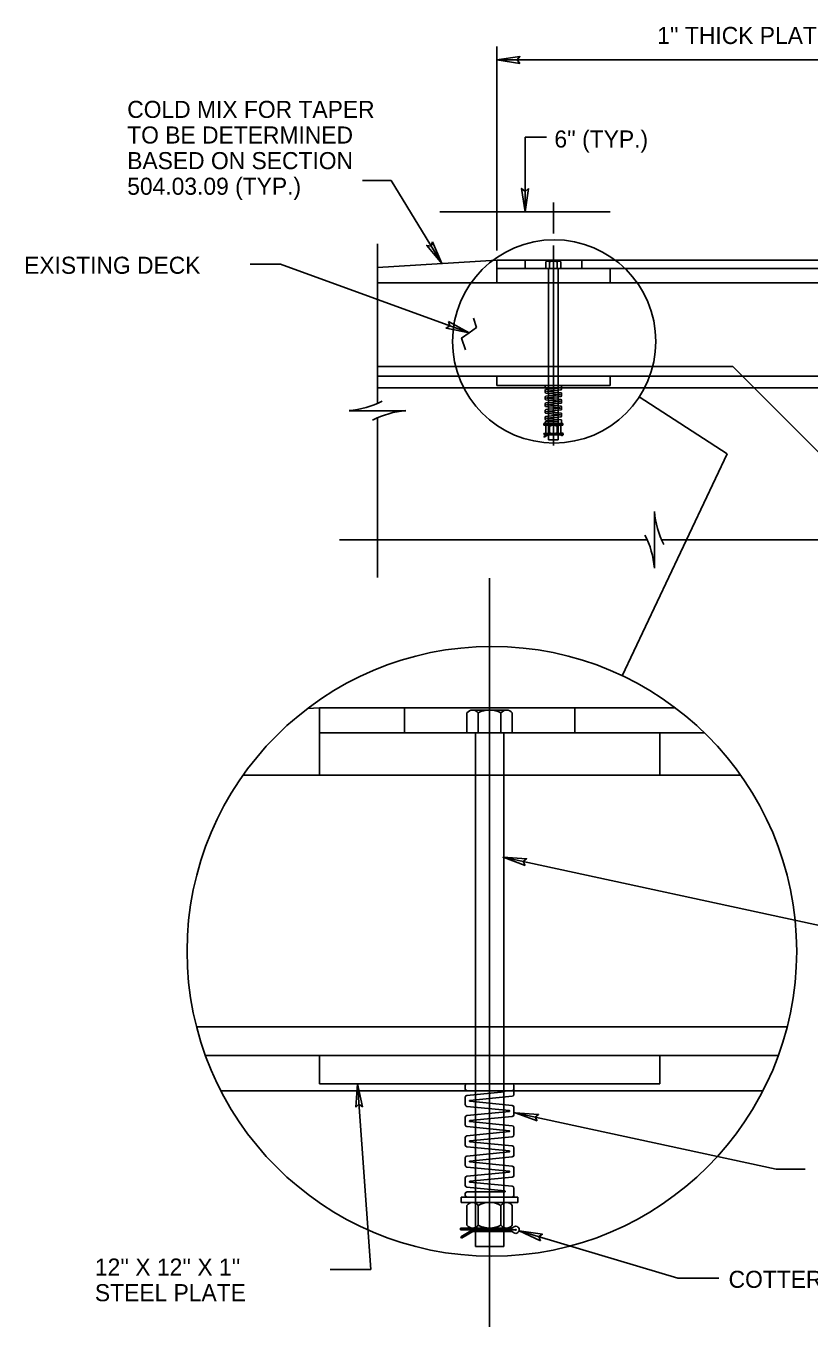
# Model space of a CAD drawing. Extents: x 12.49 to 19.62, y 5.98 to 15.32.
# Drawn here: x 12.777 to 15.532, y 10.469 to 15.04 of the extents above; entities that cross this region are included whole.
import ezdxf

# ---------------------------------------------------------------- set-up
doc = ezdxf.new("R2010")
doc.units = 0
for name, color, linetype in [('2', 7, 'Continuous'), ('Default', 7, 'Continuous'), ('DETL-DIMS', 7, 'Continuous'), ('DETL-NOTE', 7, 'Continuous'), ('V7_LEVEL_1', 7, 'Continuous')]:
    doc.layers.add(name, color=color, linetype=linetype)

msp = doc.modelspace()

# ---------------------------------------------------------------- linework, layer by layer
at = {"layer": '2'}
for p, q in [((14.232, 14.3875), (14.4313, 14.3875)), ((14.4313, 14.3875), (14.6305, 14.3875)), ((14.6305, 14.3875), (14.8298, 14.3875)), ((14.4313, 14.217), (14.0119, 14.192)), ((13.8084, 12.6445), (13.766, 12.6419))]:
    msp.add_line(p, q, dxfattribs=at)
for points in [[(13.9602, 14.4968), (14.0602, 14.4968), (14.2383, 14.2055)], [(13.5648, 14.2035), (13.6719, 14.2035), (14.3344, 13.9623)]]:
    msp.add_lwpolyline(points, dxfattribs=at)
at = {"layer": 'Default'}
for p, q in [((14.4313, 14.9686), (14.4313, 14.2511)), ((14.4313, 14.9207), (17.6199, 14.9207)), ((14.6305, 14.3117), (14.6305, 14.4197)), ((14.0119, 14.2752), (14.0119, 13.714)), ((14.6305, 13.5669), (14.6305, 14.2687)), ((14.4313, 14.217), (17.6199, 14.217)), ((14.4313, 14.1381), (14.4313, 14.217)), ((14.5309, 14.188), (14.5309, 14.217)), ((14.7302, 14.188), (14.7302, 14.217)), ((14.4313, 14.188), (14.8298, 14.188)), ((14.604, 14.188), (14.604, 14.2112)), ((14.6106, 14.2145), (14.6173, 14.2145)), ((14.6139, 13.6037), (14.6139, 14.188)), ((14.6173, 14.2145), (14.6438, 14.2145)), ((14.6173, 14.188), (14.6173, 14.2112)), ((14.6438, 14.2145), (14.6505, 14.2145)), ((14.6438, 14.188), (14.6438, 14.2112)), ((14.6471, 13.6037), (14.6471, 14.188)), ((14.6571, 14.188), (14.6571, 14.2112)), ((14.8298, 14.1381), (14.8298, 14.188)), ((14.8298, 14.188), (17.2213, 14.188)), ((14.0119, 14.1381), (14.4313, 14.1381)), ((14.4313, 14.1381), (17.6199, 14.1381)), ((14.0119, 13.8434), (15.2616, 13.8434)), ((14.0119, 13.8101), (14.4313, 13.8101)), ((14.4313, 13.7769), (14.4313, 13.8101)), ((14.4313, 13.8101), (14.8298, 13.8101)), ((14.8298, 13.7769), (14.8298, 13.8101)), ((14.8298, 13.8101), (15.9591, 13.8101)), ((15.5606, 13.5444), (15.2616, 13.8434)), ((14.0119, 13.7686), (15.9591, 13.7686)), ((14.4313, 13.7769), (14.8298, 13.7769)), ((14.6021, 13.7749), (14.6021, 13.7707)), ((14.6021, 13.7612), (14.6021, 13.7525)), ((14.6479, 13.7676), (14.604, 13.7633)), ((14.6571, 13.7622), (14.6074, 13.7574)), ((14.659, 13.7749), (14.659, 13.7643)), ((14.0285, 13.722), (14.0285, 13.722)), ((14.6021, 13.7375), (14.6021, 13.7288)), ((14.6021, 13.7139), (14.6021, 13.7051)), ((14.6537, 13.7455), (14.604, 13.7504)), ((14.6537, 13.7445), (14.604, 13.7396)), ((14.6537, 13.7218), (14.604, 13.7267)), ((14.6537, 13.7208), (14.604, 13.7159)), ((14.6571, 13.7514), (14.6074, 13.7563)), ((14.6571, 13.7386), (14.6074, 13.7337)), ((14.6571, 13.7278), (14.6074, 13.7326)), ((14.6571, 13.7149), (14.6074, 13.71)), ((14.659, 13.7494), (14.659, 13.7406)), ((14.659, 13.7257), (14.659, 13.717)), ((13.9123, 13.6887), (14.0119, 13.6887)), ((14.0119, 13.6887), (14.1116, 13.6887)), ((14.0119, 13.6887), (14.0119, 13.6887)), ((14.6021, 13.6902), (14.6021, 13.6814)), ((14.6021, 13.6665), (14.6021, 13.6578)), ((14.6537, 13.6982), (14.604, 13.703)), ((14.6537, 13.6971), (14.604, 13.6923)), ((14.6537, 13.6745), (14.604, 13.6794)), ((14.6537, 13.6735), (14.604, 13.6686)), ((14.6571, 13.7041), (14.6074, 13.709)), ((14.6571, 13.6912), (14.6074, 13.6863)), ((14.6571, 13.6804), (14.6074, 13.6853)), ((14.6571, 13.6675), (14.6074, 13.6627)), ((14.659, 13.702), (14.659, 13.6933)), ((14.659, 13.6783), (14.659, 13.6696)), ((13.9953, 13.6555), (13.9953, 13.6555)), ((14.0119, 13.6635), (14.0119, 13.1023)), ((14.5973, 13.6441), (14.6638, 13.6441)), ((14.5973, 13.6378), (14.5973, 13.6441)), ((14.5973, 13.6378), (14.6638, 13.6378)), ((14.6021, 13.6482), (14.6021, 13.6461)), ((14.6484, 13.6513), (14.604, 13.6557)), ((14.604, 13.6345), (14.604, 13.6113)), ((14.6042, 13.6503), (14.6484, 13.6503)), ((14.6571, 13.6567), (14.6074, 13.6616)), ((14.6173, 13.6345), (14.6173, 13.6113)), ((14.6438, 13.6345), (14.6438, 13.6113)), ((14.6571, 13.6345), (14.6571, 13.6113)), ((14.659, 13.6547), (14.659, 13.6461)), ((14.6638, 13.6378), (14.6638, 13.6441)), ((14.5965, 13.6079), (14.6565, 13.6079)), ((14.5965, 13.6058), (14.5965, 13.6079)), ((14.5965, 13.6058), (14.6606, 13.6058)), ((14.5967, 13.5978), (14.6104, 13.6058)), ((14.5967, 13.5978), (14.5978, 13.596)), ((14.5978, 13.596), (14.611, 13.6037)), ((14.6106, 13.6079), (14.6173, 13.6079)), ((14.611, 13.6037), (14.6565, 13.6037)), ((14.6139, 13.5861), (14.6139, 13.6037)), ((14.6139, 13.5861), (14.6471, 13.5861)), ((14.6173, 13.6079), (14.6438, 13.6079)), ((14.6438, 13.6079), (14.6505, 13.6079)), ((14.6471, 13.5861), (14.6471, 13.6037)), ((14.9855, 13.2352), (14.9855, 13.3348)), ((13.8791, 13.2352), (14.9603, 13.2352)), ((14.9523, 13.2518), (14.9523, 13.2518)), ((14.9855, 13.1356), (14.9855, 13.2352)), ((14.9855, 13.2352), (14.9855, 13.2352)), ((15.0108, 13.2352), (15.9591, 13.2352)), ((15.0187, 13.2186), (15.0187, 13.2186)), ((14.4063, 10.4694), (14.4063, 13.1007)), ((13.8084, 12.6445), (15.0594, 12.6445)), ((13.8084, 12.4078), (13.8084, 12.6445)), ((14.1074, 12.5573), (14.1074, 12.6445)), ((14.3266, 12.5573), (14.3266, 12.6268)), ((14.3466, 12.637), (14.3665, 12.637)), ((14.3665, 12.637), (14.4462, 12.637)), ((14.3665, 12.5573), (14.3665, 12.6268)), ((14.4462, 12.637), (14.4661, 12.637)), ((14.4462, 12.5573), (14.4462, 12.6268)), ((14.486, 12.5573), (14.486, 12.6268)), ((14.7053, 12.5573), (14.7053, 12.6445)), ((13.8084, 12.5573), (15.0042, 12.5573)), ((14.3565, 10.8046), (14.3565, 12.5573)), ((14.4561, 10.8046), (14.4561, 12.5573)), ((15.0042, 12.4078), (15.0042, 12.5573)), ((15.0042, 12.5573), (15.1611, 12.5573)), ((13.5398, 12.4078), (13.8084, 12.4078)), ((13.8084, 12.4078), (15.2889, 12.4078)), ((14.4538, 12.12), (15.7083, 11.8493)), ((13.3767, 11.5234), (15.452, 11.5234)), ((13.4074, 11.4238), (13.8084, 11.4238)), ((13.8084, 11.3242), (13.8084, 11.4238)), ((13.8084, 11.4238), (15.0042, 11.4238)), ((15.0042, 11.3242), (15.0042, 11.4238)), ((15.0042, 11.4238), (15.4213, 11.4238)), ((13.4618, 11.2992), (15.3669, 11.2992)), ((13.8084, 11.3242), (15.0042, 11.3242)), ((13.9889, 10.6709), (13.9419, 11.3242)), ((14.321, 11.3179), (14.321, 11.3055)), ((14.4583, 11.2961), (14.3266, 11.2832)), ((14.4917, 11.3179), (14.4917, 11.2863)), ((14.321, 11.277), (14.321, 11.2508)), ((14.4759, 11.2299), (14.3266, 11.2446)), ((14.486, 11.2801), (14.3368, 11.2654)), ((14.486, 11.2477), (14.3368, 11.2623)), ((14.321, 11.206), (14.321, 11.1797)), ((14.4759, 11.2268), (14.3266, 11.2122)), ((14.486, 11.2091), (14.3368, 11.1944)), ((14.4917, 11.2415), (14.4917, 11.2153)), ((14.4959, 11.2221), (15.4129, 11.0242)), ((14.4759, 11.1589), (14.3266, 11.1735)), ((14.4759, 11.1558), (14.3266, 11.1412)), ((14.486, 11.1767), (14.3368, 11.1913)), ((14.4917, 11.1705), (14.4917, 11.1442)), ((14.321, 11.135), (14.321, 11.1087)), ((14.486, 11.138), (14.3368, 11.1234)), ((14.486, 11.1056), (14.3368, 11.1203)), ((14.321, 11.0639), (14.321, 11.0377)), ((14.4759, 11.0879), (14.3266, 11.1025)), ((14.4759, 11.0848), (14.3266, 11.0701)), ((14.486, 11.067), (14.3368, 11.0524)), ((14.4917, 11.0994), (14.4917, 11.0732)), ((14.4759, 11.0168), (14.3266, 11.0315)), ((14.486, 11.0346), (14.3368, 11.0493)), ((14.4917, 11.0284), (14.4917, 11.0022)), ((15.4129, 11.0242), (15.5159, 11.0242)), ((14.321, 10.9929), (14.321, 10.9666)), ((14.4759, 11.0137), (14.3266, 10.9991)), ((14.486, 10.996), (14.3368, 10.9813)), ((14.486, 10.9636), (14.3368, 10.9782)), ((14.3067, 10.9256), (14.506, 10.9256)), ((14.3067, 10.9069), (14.3067, 10.9256)), ((14.321, 10.938), (14.321, 10.9318)), ((14.321, 10.938), (14.321, 10.9318)), ((14.46, 10.9474), (14.3266, 10.9604)), ((14.3272, 10.9443), (14.4598, 10.9443)), ((14.4917, 10.9574), (14.4917, 10.9318)), ((14.506, 10.9069), (14.506, 10.9256)), ((14.3067, 10.9069), (14.506, 10.9069)), ((14.3266, 10.8968), (14.3266, 10.8272)), ((14.3665, 10.8968), (14.3665, 10.8272)), ((14.4462, 10.8968), (14.4462, 10.8272)), ((14.486, 10.8968), (14.486, 10.8272)), ((14.3041, 10.8171), (14.4843, 10.8171)), ((14.3041, 10.8108), (14.3041, 10.8171)), ((14.3041, 10.8108), (14.4966, 10.8108)), ((14.3048, 10.7867), (14.346, 10.8108)), ((14.3048, 10.7867), (14.308, 10.7814)), ((14.308, 10.7814), (14.3477, 10.8046)), ((14.3466, 10.8171), (14.3665, 10.8171)), ((14.3477, 10.8046), (14.4843, 10.8046)), ((14.3565, 10.7517), (14.3565, 10.8046)), ((14.3665, 10.8171), (14.4462, 10.8171)), ((14.4462, 10.8171), (14.4661, 10.8171)), ((14.4561, 10.7517), (14.4561, 10.8046)), ((14.5101, 10.8072), (15.0677, 10.6411)), ((14.3565, 10.7517), (14.4561, 10.7517)), ((13.8466, 10.6709), (13.9889, 10.6709)), ((15.0677, 10.6411), (15.2117, 10.6411))]:
    msp.add_line(p, q, dxfattribs=at)
for centre, radius in [((14.6612, 13.6058), 0.000514), ((14.4982, 10.8108), 0.00154)]:
    msp.add_circle(centre, radius, dxfattribs=at)
for centre, radius, start, end in [((14.6106, 14.2063), 0.00822, 36.0721, 143.9279), ((14.6305, 14.1867), 0.0278, 61.4571, 118.5429), ((14.6505, 14.2063), 0.00822, 36.0721, 143.9279), ((14.6042, 13.7749), 0.00208, 90, 180), ((14.6042, 13.7707), 0.00208, 180, 270), ((14.6042, 13.7612), 0.00208, 95.6019, 180), ((14.6478, 13.7681), 0.000519, 275.6019, 90), ((14.6569, 13.7749), 0.00208, 0, 90), ((14.6569, 13.7707), 0.00208, 270, 0), ((14.6569, 13.7643), 0.00208, 275.6019, 0), ((13.8878, 13.9943), 0.3065, 274.5716, 297.3191), ((14.6042, 13.7525), 0.00208, 180, 264.3981), ((14.6042, 13.7375), 0.00208, 95.6019, 180), ((14.6042, 13.7288), 0.00208, 180, 264.3981), ((14.6042, 13.7139), 0.00208, 95.6019, 180), ((14.6074, 13.7568), 0.000519, 95.6019, 264.3982), ((14.6074, 13.7332), 0.000519, 95.6019, 264.3982), ((14.6537, 13.745), 0.000519, 275.6019, 84.3982), ((14.6537, 13.7213), 0.000519, 275.6019, 84.3982), ((14.6569, 13.7494), 0.00208, 360, 84.3981), ((14.6569, 13.7406), 0.00208, 275.6019, 0), ((14.6569, 13.7257), 0.00208, 360, 84.3981), ((14.6569, 13.717), 0.00208, 275.6019, 0), ((14.136, 13.3832), 0.3065, 94.5716, 117.3191), ((14.6042, 13.7051), 0.00208, 180, 264.3981), ((14.6042, 13.6902), 0.00208, 95.6019, 180), ((14.6042, 13.6814), 0.00208, 180, 264.3981), ((14.6042, 13.6665), 0.00208, 95.6019, 180), ((14.6074, 13.7095), 0.000519, 95.6019, 264.3982), ((14.6074, 13.6858), 0.000519, 95.6018, 264.3981), ((14.6537, 13.6976), 0.000519, 275.6019, 84.3982), ((14.6537, 13.674), 0.000519, 275.6019, 84.3982), ((14.6569, 13.702), 0.00208, 360, 84.3981), ((14.6569, 13.6933), 0.00208, 275.6018, 0), ((14.6569, 13.6783), 0.00208, 0, 84.3981), ((14.6569, 13.6696), 0.00208, 275.6019, 0), ((14.6042, 13.6578), 0.00208, 180, 264.3981), ((14.6042, 13.6482), 0.00208, 90, 180), ((14.6042, 13.6461), 0.00208, 180, 270), ((14.6106, 13.6296), 0.00822, 36.0721, 143.9279), ((14.6074, 13.6621), 0.000519, 95.6019, 264.3982), ((14.6305, 13.61), 0.0278, 61.4571, 118.5429), ((14.6505, 13.6296), 0.00822, 36.0721, 143.9279), ((14.6484, 13.6508), 0.000519, 270, 84.3981), ((14.6569, 13.6461), 0.00208, 270, 0), ((14.6569, 13.6547), 0.00208, 0, 84.3981), ((14.6106, 13.6161), 0.00822, 216.0721, 323.9279), ((14.6305, 13.6357), 0.0278, 241.4571, 298.5429), ((14.6505, 13.6161), 0.00822, 216.0721, 323.9279), ((14.6565, 13.61), 0.00208, 270, 318.007), ((14.6565, 13.6017), 0.00208, 41.6281, 90), ((14.6612, 13.6058), 0.00415, 221.6281, 138.007), ((15.2911, 13.3593), 0.3065, 184.5716, 207.3191), ((14.68, 13.1111), 0.3065, 4.5716, 27.3191), ((14.3466, 12.6123), 0.0246, 36.0721, 143.9279), ((14.4063, 12.5536), 0.0834, 61.4571, 118.5429), ((14.4661, 12.6123), 0.0246, 36.0721, 143.9279), ((14.3272, 11.3179), 0.00623, 90, 180), ((14.3272, 11.3055), 0.00623, 180, 270), ((14.4581, 11.2977), 0.00156, 275.6019, 90), ((14.4854, 11.3179), 0.00623, 0, 90), ((14.4854, 11.3055), 0.00623, 270, 0), ((14.3272, 11.277), 0.00623, 95.6019, 180), ((14.3272, 11.2508), 0.00623, 180, 264.3981), ((14.3369, 11.2639), 0.00156, 95.6019, 264.3982), ((14.4854, 11.2863), 0.00623, 275.6019, 0), ((14.4854, 11.2415), 0.00623, 360, 84.3981), ((14.3272, 11.206), 0.00623, 95.6019, 180), ((14.4757, 11.2284), 0.00156, 275.6019, 84.3982), ((14.4854, 11.2153), 0.00623, 275.6019, 0), ((14.3272, 11.1797), 0.00623, 180, 264.3981), ((14.3369, 11.1929), 0.00156, 95.6019, 264.3982), ((14.4757, 11.1573), 0.00156, 275.6019, 84.3982), ((14.4854, 11.1705), 0.00623, 360, 84.3981), ((14.3272, 11.135), 0.00623, 95.6019, 180), ((14.3272, 11.1087), 0.00623, 180, 264.3981), ((14.3369, 11.1218), 0.00156, 95.6019, 264.3982), ((14.4854, 11.1442), 0.00623, 275.6019, 0), ((14.3272, 11.0639), 0.00623, 95.6019, 180), ((14.4757, 11.0863), 0.00156, 275.6019, 84.3982), ((14.4854, 11.0994), 0.00623, 360, 84.3981), ((14.4854, 11.0732), 0.00623, 275.6018, 0), ((14.3272, 11.0377), 0.00623, 180, 264.3981), ((14.3369, 11.0508), 0.00156, 95.6018, 264.3981), ((14.4757, 11.0153), 0.00156, 275.6019, 84.3982), ((14.4854, 11.0284), 0.00623, 0, 84.3981), ((14.3272, 10.9929), 0.00623, 95.6019, 180), ((14.3369, 10.9798), 0.00156, 95.6019, 264.3982), ((14.4854, 11.0022), 0.00623, 275.6019, 0), ((14.3272, 10.9666), 0.00623, 180, 264.3981), ((14.3272, 10.938), 0.00623, 90, 180), ((14.3272, 10.9318), 0.00623, 180, 270), ((14.3272, 10.9318), 0.00623, 180, 270), ((14.4598, 10.9458), 0.00156, 270, 84.3981), ((14.4854, 10.9318), 0.00623, 270, 0), ((14.4854, 10.9318), 0.00623, 270, 0), ((14.4854, 10.9574), 0.00623, 0, 84.3981), ((14.3466, 10.8822), 0.0246, 36.0721, 143.9279), ((14.4063, 10.8235), 0.0834, 61.4571, 118.5429), ((14.4661, 10.8822), 0.0246, 36.0721, 143.9279), ((14.3466, 10.8417), 0.0246, 216.0721, 323.9279), ((14.4063, 10.9005), 0.0834, 241.4571, 298.5429), ((14.4661, 10.8417), 0.0246, 216.0721, 323.9279), ((14.4842, 10.7984), 0.00623, 41.6281, 90), ((14.4843, 10.8233), 0.00623, 270, 318.007), ((14.4982, 10.8108), 0.0125, 221.6281, 138.007)]:
    msp.add_arc(centre, radius, start, end, dxfattribs=at)
at = {"layer": 'DETL-DIMS'}
for p, q in [((14.5131, 14.9326), (14.4313, 14.9207)), ((14.5131, 14.9088), (14.4313, 14.9207)), ((14.5131, 14.9326), (14.503, 14.9207)), ((14.5131, 14.9088), (14.503, 14.9207)), ((14.519, 14.4693), (14.5309, 14.3875)), ((14.519, 14.4693), (14.5309, 14.4592)), ((14.5428, 14.4693), (14.5309, 14.3875)), ((14.5428, 14.4693), (14.5309, 14.4592)), ((14.1855, 14.2691), (14.2383, 14.2055)), ((14.1855, 14.2691), (14.2009, 14.2667)), ((14.2058, 14.2815), (14.2009, 14.2667)), ((14.2058, 14.2815), (14.2383, 14.2055)), ((14.2534, 13.9791), (14.267, 13.9868)), ((14.2616, 14.0014), (14.3344, 13.9623)), ((14.2616, 14.0014), (14.267, 13.9868)), ((14.2534, 13.9791), (14.3344, 13.9623)), ((14.5363, 12.1144), (14.4538, 12.12)), ((14.5313, 12.0911), (14.4538, 12.12)), ((14.5363, 12.1144), (14.5239, 12.1049)), ((14.5313, 12.0911), (14.5239, 12.1049)), ((13.9359, 11.2417), (13.9419, 11.3242)), ((13.9596, 11.2434), (13.9419, 11.3242)), ((13.9359, 11.2417), (13.947, 11.2526)), ((13.9596, 11.2434), (13.947, 11.2526)), ((14.5784, 11.2164), (14.4959, 11.2221)), ((14.5734, 11.1932), (14.4959, 11.2221)), ((14.5784, 11.2164), (14.566, 11.2069)), ((14.5734, 11.1932), (14.566, 11.2069)), ((14.5919, 10.7953), (14.5101, 10.8072)), ((14.5851, 10.7725), (14.5101, 10.8072)), ((14.5919, 10.7953), (14.5788, 10.7868)), ((14.5851, 10.7725), (14.5788, 10.7868))]:
    msp.add_line(p, q, dxfattribs=at)
for points in [[(14.5131, 14.9088), (14.4313, 14.9207), (14.5131, 14.9326), (14.503, 14.9207)], [(14.5428, 14.4693), (14.5309, 14.3875), (14.519, 14.4693), (14.5309, 14.4592)], [(14.2058, 14.2815), (14.2383, 14.2055), (14.1855, 14.2691), (14.2009, 14.2667)], [(14.2616, 14.0014), (14.3344, 13.9623), (14.2534, 13.9791), (14.267, 13.9868)], [(14.5313, 12.0911), (14.4538, 12.12), (14.5363, 12.1144), (14.5239, 12.1049)], [(13.9359, 11.2417), (13.9419, 11.3242), (13.9596, 11.2434), (13.947, 11.2526)], [(14.5734, 11.1932), (14.4959, 11.2221), (14.5784, 11.2164), (14.566, 11.2069)], [(14.5851, 10.7725), (14.5101, 10.8072), (14.5919, 10.7953), (14.5788, 10.7868)]]:
    msp.add_lwpolyline(points, close=True, dxfattribs=at)
at = {"layer": 'V7_LEVEL_1'}
for p, q in [((14.5309, 14.3875), (14.5309, 14.6499)), ((14.5309, 14.6499), (14.6068, 14.6499)), ((14.6042, 13.7686), (14.6569, 13.7686)), ((14.9325, 13.7372), (15.2407, 13.5367)), ((15.2407, 13.5367), (14.8723, 12.7576)), ((14.3272, 11.2992), (14.4854, 11.2992))]:
    msp.add_line(p, q, dxfattribs=at)
msp.add_lwpolyline([(14.3211, 13.903), (14.3076, 13.9435), (14.3344, 13.9623), (14.3603, 13.9813), (14.3495, 14.0137)], dxfattribs=at)
for centre, radius in [((14.6332, 13.932), 0.3571), ((14.4144, 11.7892), 1.0712)]:
    msp.add_circle(centre, radius, dxfattribs=at)

# ---------------------------------------------------------------- texts
at = {"layer": 'DETL-NOTE'}
for s, p in [("1'' THICK PLATE (4'-0'' TO 8'-0'' WIDE)", (14.9953, 14.9769)), ('COLD MIX FOR TAPER', (13.1328, 14.7172)), ('TO BE DETERMINED ', (13.1328, 14.6272)), ("6'' (TYP.)", (14.634, 14.6131)), ('BASED ON SECTION', (13.1328, 14.5372)), ('504.03.09 (TYP.) ', (13.1328, 14.4472)), ('EXISTING DECK', (12.7705, 14.1696)), ('COTTER PIN', (15.2462, 10.6069))]:
    msp.add_text(s, height=0.06, dxfattribs=at).set_placement(p)
at = {"layer": 'V7_LEVEL_1'}
for s, p in [("12'' X 12'' X 1''", (13.0192, 10.6499)), ('STEEL PLATE', (13.0192, 10.5599))]:
    msp.add_text(s, height=0.06, dxfattribs=at).set_placement(p)

doc.saveas('drawing.dxf')
